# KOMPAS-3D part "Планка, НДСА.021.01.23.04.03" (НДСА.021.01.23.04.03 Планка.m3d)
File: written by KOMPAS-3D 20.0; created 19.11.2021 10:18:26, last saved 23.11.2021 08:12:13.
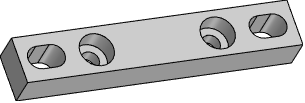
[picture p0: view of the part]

Document properties: Полное имя файла: C:\Users\s.pischagina\Desktop\PLM\НДСА.021.01.23.04.03 Планка.m3d

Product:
- Part/product: Планка  | designation НДСА.021.01.23.04.03
    Материал: АМг6  ГОСТ 4784-2019 (density 2640 kg/m3)
    Масса: 0.0238069
    additional columns: <item xmlns="http://appius.ru/pdm" xmlns:xs="http://www.w3.org/2001/XMLSchema" x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; <item xmlns="http://appius.ru/pdm" xmlns:xs="http://www.w3.org/2001/XMLSchema" x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; <item xmlns="http://appius.ru/pdm" xmlns:xs="http://www.w3.org/2001/XMLSchema" x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
    source file: НДСА.021.01.23.04.03 Планка.cdw

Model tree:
1. Эскиз:1
2. Элемент выдавливания:1
     Расстояние 1 = 10
3. Эскиз:2  (with: Элемент выдавливания:1)
4. Элемент выдавливания:2
     Расстояние 2 = 6
5. Эскиз:3  (with: Элемент выдавливания:1)
6. Элемент выдавливания:3  (labels: АМг6  ГОСТ 4784-2019)
     Расстояние 2 = 10

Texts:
  НДСА.021.01.23.04.03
